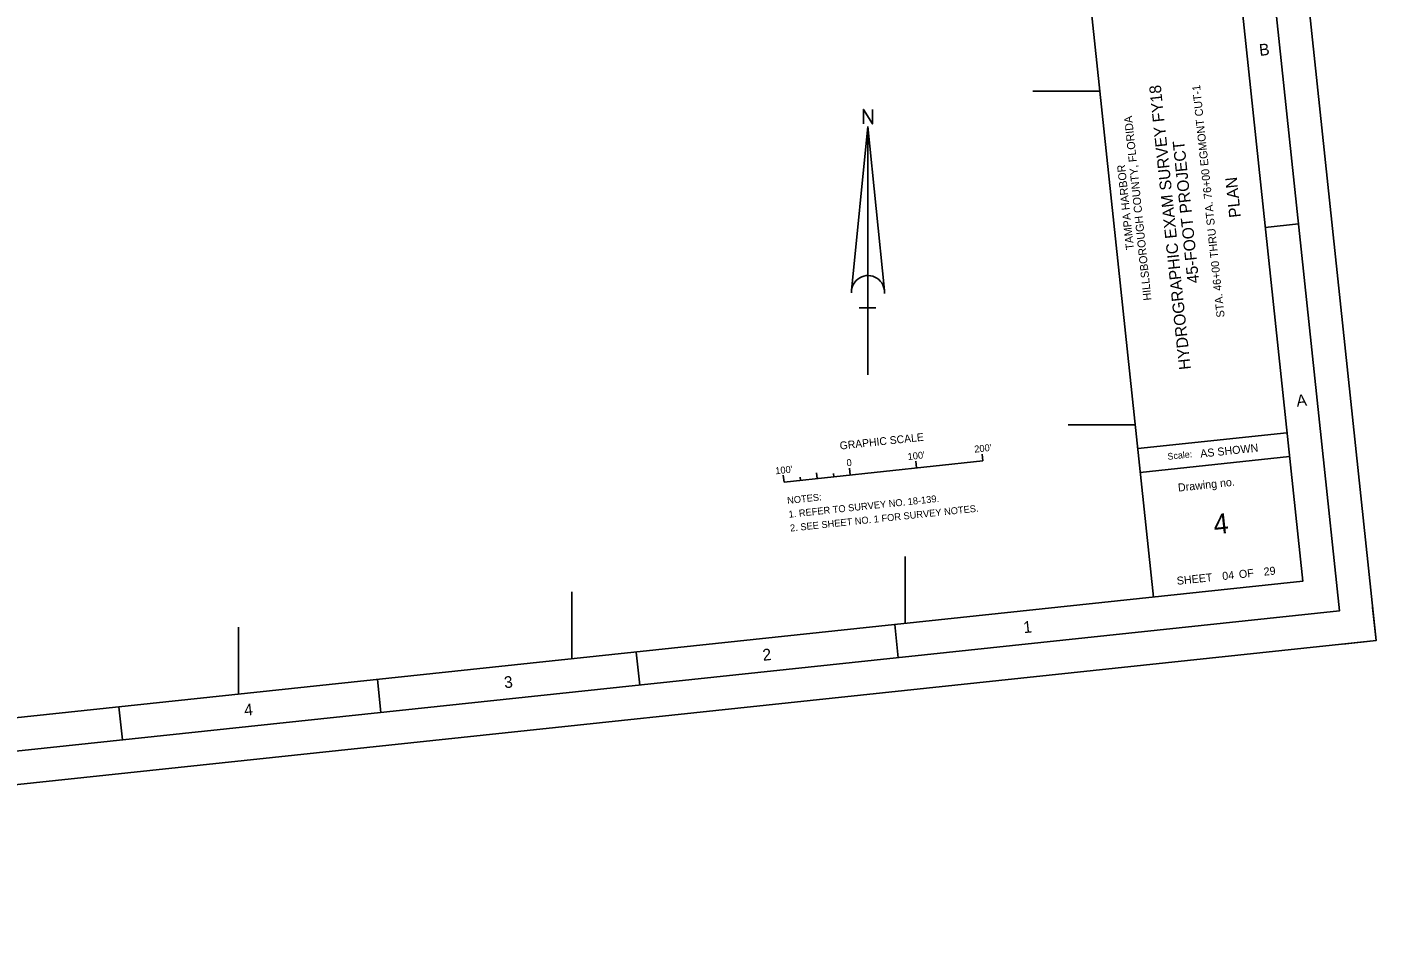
# Model space of a CAD drawing. Extents: x 341472 to 346206, y 1184213 to 1188058.
# Drawn here: x 344183 to 346206, y 1184213 to 1185596 of the extents above; entities that cross this region are included whole.
import ezdxf

# ---------------------------------------------------------------- set-up
doc = ezdxf.new("R2010")
doc.units = 0
for name, color, linetype in [('G-ANNO-NPLT', 7, 'Continuous'), ('G-ANNO-TEXT-DRWG', 7, 'Continuous'), ('G-ANNO-TEXT-PROJ', 7, 'Continuous'), ('G-ANNO-TEXT-TTLB', 7, 'Continuous'), ('G-ANNO-TTLB', 7, 'Continuous'), ('V-ANNO-NOTE', 7, 'Continuous'), ('V-ANNO-SYMB', 7, 'Continuous'), ('V-TOPO-COOR-STAT', 7, 'Continuous')]:
    doc.layers.add(name, color=color, linetype=linetype)

msp = doc.modelspace()

# ---------------------------------------------------------------- linework, layer by layer
at = {"layer": 'G-ANNO-NPLT'}
msp.add_lwpolyline([(341472, 1187593.7), (345847.5, 1188057.5), (346205.9, 1184676.5), (341830.4, 1184212.7)], close=True, dxfattribs=at)
msp.add_lwpolyline([(346200.6, 1184726.2), (346205.9, 1184676.5), (346156.1, 1184671.2)], dxfattribs=at)
at = {"layer": 'G-ANNO-TTLB'}
for p, q in [((345534.8, 1187923.8), (345872.1, 1184741.6)), ((346089.4, 1185301), (346039.7, 1185295.7)), ((345848.5, 1184964.2), (346072.3, 1184987.9)), ((345852.3, 1184928.7), (346076, 1184952.4)), ((345489.6, 1184650.8), (345484.3, 1184700.5)), ((345101.8, 1184609.7), (345096.5, 1184659.4)), ((344713.9, 1184568.6), (344708.7, 1184618.3)), ((344326.1, 1184527.5), (344320.8, 1184577.2))]:
    msp.add_line(p, q, dxfattribs=at)
for points in [[(341874.8, 1184267.7), (346150.9, 1184720.9), (345803, 1188002.5), (341527, 1187549.3)], [(345758.6, 1187947.5), (341656.6, 1187512.7), (341993.9, 1184330.6), (346095.9, 1184765.4)]]:
    msp.add_lwpolyline(points, close=True, dxfattribs=at)
at = {"layer": 'V-ANNO-NOTE'}
for p, q in [((345318.2, 1184914.2), (345616.5, 1184945.8)), ((345517, 1184935.3), (345515.9, 1184945.6)), ((345616.5, 1184945.8), (345615.4, 1184956.2)), ((345318.2, 1184914.2), (345317.1, 1184924.6)), ((345343, 1184916.8), (345342.5, 1184921.6)), ((345367.9, 1184919.4), (345367, 1184927.9)), ((345392.7, 1184922.1), (345392.2, 1184926.8)), ((345417.6, 1184924.7), (345416.5, 1184935.1)), ((345417.6, 1184924.7), (345416.5, 1184935.1)), ((345417.6, 1184924.7), (345417.1, 1184929.7))]:
    msp.add_line(p, q, dxfattribs=at)
at = {"layer": 'V-ANNO-SYMB'}
for p, q in [((345419.4, 1185201.4), (345444.1, 1185447.1)), ((345444.1, 1185074.8), (345444.1, 1185447.1)), ((345468.8, 1185201.4), (345444.1, 1185447.1)), ((345455.8, 1185175.3), (345431, 1185175.3))]:
    msp.add_line(p, q, dxfattribs=at)
msp.add_lwpolyline([(345437.2, 1185451.1), (345437.2, 1185472.8), (345450.7, 1185451.1), (345450.7, 1185472.8)], dxfattribs=at)
msp.add_arc((345444.1, 1185198.9), 24.8, 355.2984, 182.0673, dxfattribs=at)
at = {"layer": 'V-TOPO-COOR-STAT'}
for p, q in [((345691.2, 1185500), (345791.7, 1185500)), ((345744.2, 1185000), (345844.7, 1185000)), ((345500, 1184702.2), (345500, 1184802.8)), ((345000, 1184649.2), (345000, 1184749.8)), ((344500, 1184596.2), (344500, 1184696.8))]:
    msp.add_line(p, q, dxfattribs=at)

# ---------------------------------------------------------------- texts
at = {"layer": 'G-ANNO-TEXT-DRWG'}
for s, height, rotation, p in [('STA. 46+00 THRU STA. 76+00 EGMONT CUT-1', 12, 96.0506, (345978.9, 1185161.5)), ('PLAN', 17.5, 96.0506, (346003.4, 1185311.4)), ('4', 30, 6.0506, (345963.7, 1184835.6)), (' 04          29', 12, 6.0506, (345971.5, 1184766.7))]:
    msp.add_text(s, height=height, rotation=rotation, dxfattribs=at).set_placement(p)
at = {"layer": 'G-ANNO-TEXT-PROJ'}
for s, height, p in [('HYDROGRAPHIC EXAM SURVEY FY18', 17.5, (345928.2, 1185083.4)), ('HILLSBOROUGH COUNTY, FLORIDA', 12, (345869.2, 1185186.9)), ('45-FOOT PROJECT', 17.5, (345940.8, 1185213.1)), ('TAMPA HARBOR', 12, (345843, 1185262.9))]:
    msp.add_text(s, height=height, rotation=96.0506, dxfattribs=at).set_placement(p)
at = {"layer": 'G-ANNO-TEXT-TTLB'}
for s, height, p in [('Scale:', 10, (345893.7, 1184947.4)), ('AS SHOWN', 12, (345942.9, 1184950.7)), ('Drawing no.', 12, (345909.5, 1184899.8)), ('SHEET         OF', 12, (345907.8, 1184760))]:
    msp.add_text(s, height=height, rotation=6.0506, dxfattribs=at).set_placement(p)
at = {"layer": 'G-ANNO-TTLB'}
for s, p in [('B', (346031.5, 1185552.9)), ('A', (346087.3, 1185027.1)), ('1', (345677.8, 1184687.5)), ('2', (345286.9, 1184646.1)), ('3', (344899.3, 1184605)), ('4', (344509.6, 1184563.7))]:
    msp.add_text(s, height=17.5, rotation=6.0506, dxfattribs=at).set_placement(p)
at = {"layer": 'V-ANNO-NOTE'}
for s, height, p in [('GRAPHIC SCALE', 11.666, (345402.3, 1184962.8)), ("100'", 10.42, (345504.1, 1184947.1)), ("200'", 10.42, (345604, 1184958.2)), ("100'", 10.42, (345305.6, 1184925.7)), ('0', 10.4, (345412.5, 1184937.7)), ('NOTES:', 10.42, (345323.4, 1184881.3)), ('1. REFER TO SURVEY NO. 18-139.', 10.416, (345325.6, 1184860.6)), ('2. SEE SHEET NO. 1 FOR SURVEY NOTES.', 10.416, (345327.8, 1184839.9))]:
    msp.add_text(s, height=height, rotation=6.0506, dxfattribs=at).set_placement(p)

doc.saveas('drawing.dxf')
